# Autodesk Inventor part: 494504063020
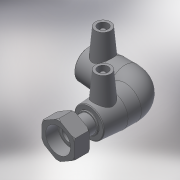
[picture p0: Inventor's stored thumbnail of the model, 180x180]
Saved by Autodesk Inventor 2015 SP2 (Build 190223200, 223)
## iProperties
Created: 2017-06
Part Number: 494504063020
Material: Generic
Description: PLASSON 90° ELBOW FEMALE FREE NUT TRANSITION 63-2"
Document SubType Name: Modeling
Designer: KIM
Mass: 55.0731 g
Surface Area: 148.067 cm^2
Volume: 55.0731 cm^3
Density: 1 g/cm^3
Appearance: Default
Author: KIM
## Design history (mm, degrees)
derived "494504.ipt"
feature "Solid1::494504.ipt"
tag "TaggingFeature1"
body "Solid1"
other parameters: "d2" = 82, "d4" = 43.66667, "d5" = 73.8, "d8" = 168 deg, "d10" = 22.8, "d11" = 7.6, "d29" = 59, "d30" = 15, "d31" = 72.05, "d34" = 5 deg, "d41" = 4, "d42" = 14, "d43" = 0, "d49" = 63, "d50" = 53.55, "d51" = 22.8, "d52" = 57, "d54" = 90 deg, "d57" = 63, "d58" = 57, "d59" = 0, "d61" = 90 deg, "d86" = 3, "d87" = 0, "d97" = 41, "d98" = 44, "d99" = 84.984, "d109" = 1.26, "d116" = 22, "d117" = 56.656, "d118" = 17.6, "d119" = 1.76, "d120" = 45.3248, "d121" = 1.76, "d122" = 48.1576, "d123" = 41, "d124" = 2.8328, "d128" = 0, "d_" = 63, "L_" = 175, "L_1" = 57, "D_" = 41, "A_" = 59, "d_2" = 12, "L_2" = 44, "D_1" = 82, "G_" = 56.656
